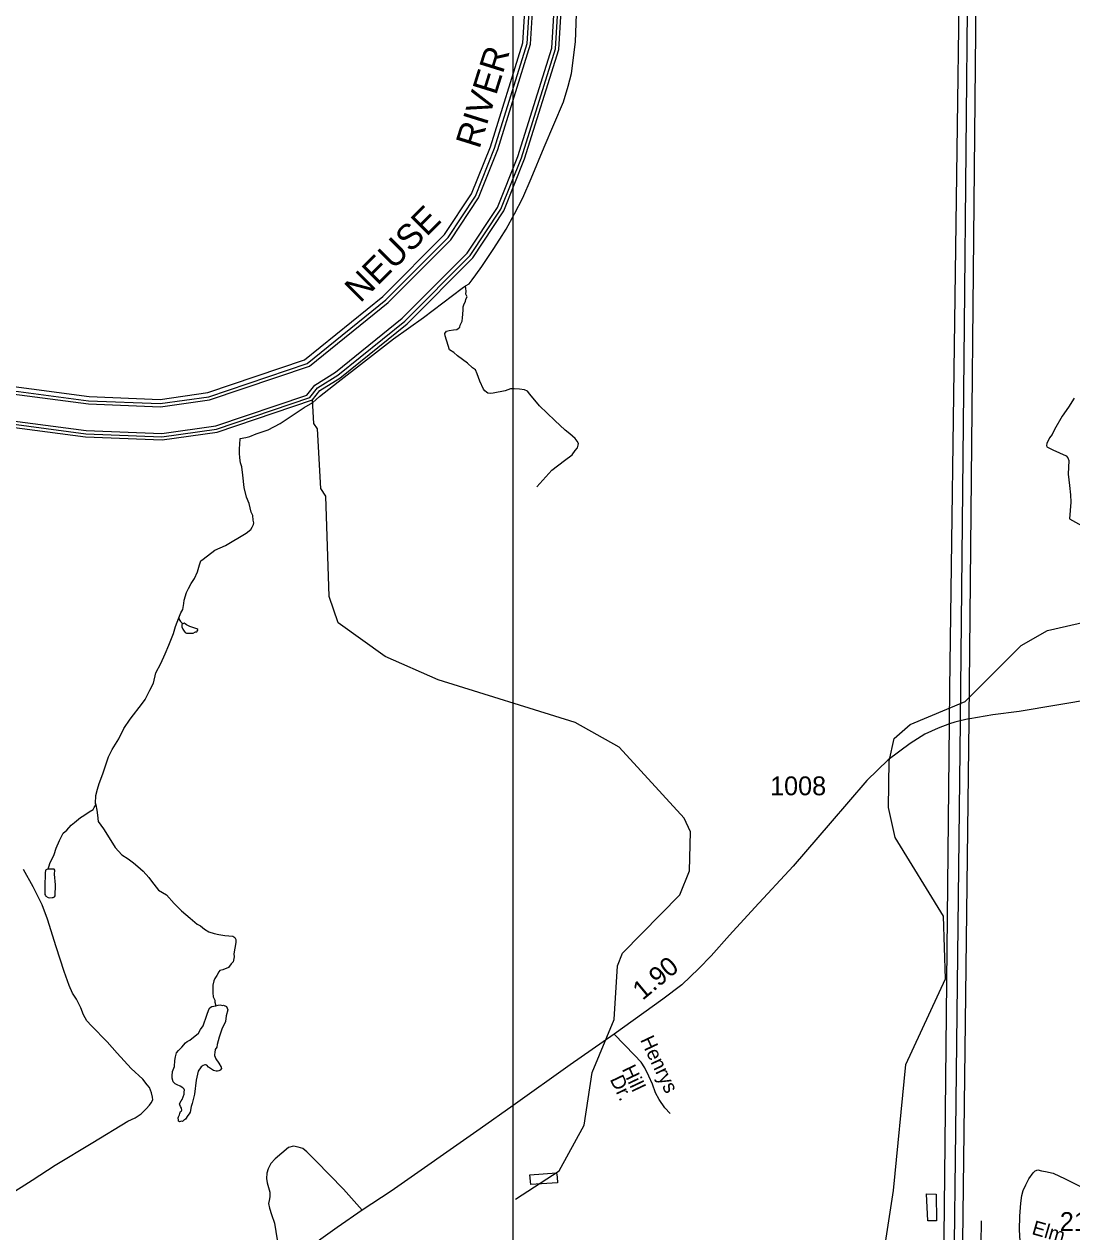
# Model space of a CAD drawing. Extents: x 2206922 to 2357709, y 510027 to 673830.
# Drawn here: x 2263859 to 2270812, y 583195 to 591205 of the extents above; entities that cross this region are included whole.
import ezdxf

# ---------------------------------------------------------------- set-up
doc = ezdxf.new("R2010")
doc.units = 0
for name, color, linetype in [('Exist Hydrographic Buffer Line', 7, 'Continuous'), ('Exist Hydrographic Creek Single Shore', 7, 'Continuous'), ('Exist Hydrographic Misc Water Feature', 7, 'Continuous'), ('Exist Hydrographic River Shore', 7, 'Continuous'), ('Exist Hydrographic River Shore Label', 7, 'Continuous'), ('Exist Road Non-System Type 51', 7, 'Continuous'), ('Exist Road Non-System Type 51 Label', 7, 'Continuous'), ('Exist Road Secondary Mileage Hundredths English Label', 7, 'Continuous'), ('Exist Road Secondary Type 51 Attributed', 7, 'Continuous'), ('Exist Road Secondary Type 51 Label', 7, 'Continuous'), ('Exist Road Secondary Type 51 Number Label', 7, 'Continuous'), ('Exist Utilities Electrical Transmission Line', 7, 'Continuous'), ('Map Preparation Inset Cut Line', 7, 'Continuous')]:
    doc.layers.add(name, color=color, linetype=linetype)

msp = doc.modelspace()

# ---------------------------------------------------------------- linework, layer by layer
at = {"layer": 'Exist Hydrographic Buffer Line'}
for points in [[(2265738.1, 588954.9), (2266258.8, 589376.1), (2266672.7, 589790.2), (2266854.1, 590065.1), (2266981.1, 590382.3), (2267198, 591076.7), (2267226.2, 591537.3), (2267426.9, 592727.2)], [(2265752.3, 588937.3), (2266273.9, 589359.2), (2266690.3, 589775.8), (2266874.3, 590054.5), (2267002.4, 590374.7), (2267220.4, 591072.6), (2267248.7, 591534.7), (2267449.3, 592723.5)], [(2265735, 588744.5), (2265789.1, 588811.1), (2265925.5, 588896.4), (2266368.2, 589254.5), (2266800, 589686.4), (2266999.6, 589989), (2267135.1, 590327.5), (2267359.8, 591047), (2267388.7, 591518.6), (2267586.4, 592690.4)], [(2265754.7, 588729.4), (2265805.7, 588792.3), (2265939.9, 588876.2), (2266384.8, 589236.1), (2266819.2, 589670.7), (2267021.7, 589977.4), (2267158.5, 590319.2), (2267384.3, 591042.4), (2267413.4, 591515.8), (2267610.4, 592683.8)], [(2260871, 587572.6), (2260946.2, 587608.4), (2260953.7, 587654.2), (2261804, 588398.4), (2262148.5, 588603.7), (2262761.1, 588772.7), (2262990.7, 588802.1), (2263521.7, 588808.8), (2264287.1, 588707.3), (2264762.3, 588688.4), (2265084.8, 588733.9), (2265738.1, 588954.9)], [(2260883.1, 587554.9), (2260965.4, 587594), (2260973.5, 587643.2), (2261816.6, 588381.1), (2262156.9, 588584.1), (2262765.3, 588751.8), (2262992.2, 588780.9), (2263520.5, 588787.5), (2264285.2, 588686.1), (2264763.4, 588667.2), (2265089.7, 588713.2), (2265752.3, 588937.3)], [(2261050.1, 587440), (2261131, 587509.5), (2261137.9, 587551.8), (2261921.1, 588237.3), (2262227.1, 588419.7), (2262800.2, 588577.7), (2263004.6, 588603.9), (2263509.9, 588610.3), (2264270.1, 588509.5), (2264772.3, 588489.6), (2265130.8, 588540.1), (2265735, 588744.5)], [(2261059.1, 587420.5), (2261150.1, 587498.8), (2261157.1, 587541.2), (2261933.2, 588220.5), (2262235.2, 588400.6), (2262804.3, 588557.5), (2263006, 588583.3), (2263508.6, 588589.7), (2264268.3, 588489), (2264773.4, 588468.9), (2265135.6, 588520), (2265754.7, 588729.4)]]:
    msp.add_lwpolyline(points, dxfattribs=at)
at = {"layer": 'Exist Hydrographic Creek Single Shore'}
msp.add_lwpolyline([(2267120.6, 583412.2), (2267410.6, 583599.8), (2267574.6, 583901.5), (2267629.6, 584251.4), (2267775.6, 584602.6), (2267797.5, 584959.7), (2267830.5, 585044.2), (2268209.5, 585430.1), (2268274.5, 585589.5), (2268280.6, 585848.5), (2268238.6, 585937.9), (2267808.6, 586409), (2267515.6, 586572.3), (2266605.5, 586856.4), (2266254.5, 587011.1), (2265943.4, 587233.9), (2265883.6, 587408.9), (2265860.6, 588075.1), (2265827.6, 588125), (2265806.5, 588522.3), (2265781.4, 588555.6), (2265771.6, 588713.2)], dxfattribs=at)
at = {"layer": 'Exist Hydrographic Misc Water Feature'}
for points in [[(2266787, 589469.4), (2266812.2, 589483.4), (2266832.3, 589509.6), (2266856.1, 589542.1), (2266895.7, 589598.2), (2266970.5, 589711), (2267015.8, 589779.2), (2267057.1, 589845.6), (2267114.1, 589948.1), (2267168.8, 590052.6), (2267223.8, 590181), (2267309.7, 590389.9), (2267439.1, 590690.7), (2267470.2, 590793.1), (2267491.4, 590877.1), (2267517, 591087.3), (2267528.3, 591397.5), (2267540.2, 591621.2), (2267594.5, 591981.6), (2267637, 592161.8), (2267688.4, 592430.2), (2267758.3, 592666.6), (2267758.1, 592678.8)], [(2265774.7, 588696.2), (2265820, 588736.8), (2265943.4, 588833.8), (2266112, 588963.3), (2266310.5, 589119.1), (2266508.8, 589258.7), (2266766.7, 589455), (2266787, 589469.4)], [(2267261.3, 588136.3), (2267361.8, 588247.3), (2267445.2, 588312.2), (2267495.1, 588348.5), (2267516.4, 588376.9), (2267530.5, 588395.1), (2267536.5, 588412.8), (2267538.5, 588425), (2267530.1, 588438.9), (2267515.8, 588456.9), (2267479.3, 588488.3), (2267449.5, 588511.8), (2267381, 588577.3), (2267280, 588674.5), (2267215.4, 588751.5), (2267199.2, 588771.4), (2267179.3, 588779.3), (2267146.9, 588785), (2267111.2, 588786.7), (2267087, 588786.7), (2267051.3, 588774.2), (2266971.6, 588757.5), (2266951.3, 588755.3), (2266935.5, 588757.2), (2266927.3, 588765), (2266917.2, 588773), (2266906.8, 588784.7), (2266882.8, 588836.5), (2266864.3, 588886.4), (2266854.1, 588912.2), (2266834, 588926.2), (2266801.4, 588955.9), (2266735.1, 589005.2), (2266710.7, 589026.7), (2266682.6, 589044.7), (2266672.4, 589074.7), (2266654.1, 589138.3), (2266651.7, 589154.1), (2266661.7, 589168.4), (2266679.8, 589174.6), (2266709.3, 589178.6), (2266729.6, 589180.8), (2266739.6, 589187), (2266749.5, 589195.3), (2266753, 589209.3), (2266765.1, 589235.1), (2266768.8, 589257.2), (2266772.2, 589309.4), (2266772, 589331.3), (2266778, 589351.2), (2266788, 589365.5), (2266789.5, 589381.5), (2266799.7, 589397.4), (2266791.1, 589415.2), (2266791.3, 589433.5), (2266787, 589469.4)], [(2265293, 588456.1), (2265330.9, 588464.2), (2265357.2, 588470.4), (2265398.8, 588488.8), (2265478.6, 588513.7), (2265557.9, 588556.5), (2265717, 588661.9), (2265774.7, 588696.2)], [(2270827.6, 588725.4), (2270790.4, 588665.3), (2270746.8, 588605), (2270697.6, 588516.3), (2270682, 588484.2), (2270664.3, 588462.1), (2270646.5, 588424.2), (2270642.6, 588410.2), (2270645.1, 588402.1), (2270686.7, 588382.4), (2270773.4, 588341.4), (2270785.5, 588329.5), (2270791.9, 588311.5), (2270788.4, 588219.5), (2270795.2, 588145.5), (2270803.6, 588083.8), (2270804.2, 588035.5), (2270797, 587923.8), (2270936, 587846.9)], [(2264886.4, 587266.8), (2264899.7, 587300.8), (2264911.8, 587322.9), (2264919.4, 587362.7), (2264921.2, 587384.8), (2264937, 587435.1), (2264950.6, 587463.1), (2264968.2, 587495.3), (2264989.9, 587529.3), (2265009.4, 587573.8), (2265022.9, 587619.7), (2265030.7, 587645.6), (2265046.7, 587655.8), (2265124, 587716.7), (2265195.8, 587747.2), (2265333.2, 587828.4), (2265362.7, 587852.7), (2265372.6, 587869), (2265380.1, 587887), (2265382.2, 587898.8), (2265378.1, 587914.9), (2265375.8, 587946.9), (2265365.4, 587968.7), (2265351.2, 588026.8), (2265334.8, 588068.6), (2265319.9, 588132.5), (2265309.2, 588214), (2265304.7, 588268.2), (2265294.4, 588296.1), (2265290.5, 588328), (2265288.1, 588359.9), (2265287.7, 588390), (2265289.7, 588417.7), (2265293, 588456.1)], [(2264332.1, 586036.3), (2264335.6, 586088.1), (2264345.2, 586132.2), (2264357.1, 586168.4), (2264380.1, 586232.7), (2264419.3, 586344.8), (2264442.4, 586394.8), (2264486.5, 586465.3), (2264521.6, 586533.7), (2264562.6, 586596.1), (2264643.8, 586702.7), (2264661.4, 586726.8), (2264693, 586786.9), (2264716.4, 586835.3), (2264732, 586903.6), (2264767, 586963.9), (2264794.7, 587029.9), (2264818.5, 587086), (2264849.5, 587164.4), (2264863, 587210.6), (2264886.4, 587266.8)], [(2264886.4, 587266.8), (2264888.6, 587256.7), (2264896.8, 587242.9), (2264912.8, 587227)], [(2269493.5, 582593.5), (2269627.6, 583469.7), (2269710.6, 584304.3), (2269972.5, 584873), (2269960.6, 585289.7), (2269638.7, 585811.2), (2269594.6, 586008.8), (2269600.5, 586317), (2269632.5, 586467.2), (2269739.6, 586560.1), (2270104.5, 586713.4), (2270476.5, 587083.1), (2270649.6, 587184.5), (2271007.6, 587265.8)], [(2264912.8, 587227), (2264905, 587223), (2264905.2, 587208.7), (2264911, 587192.8), (2264921, 587179.2), (2264927, 587171), (2264935.4, 587165.3), (2264941.3, 587165.2), (2264957.5, 587165.2), (2264981.3, 587165.6), (2264997.1, 587173.8), (2265005.1, 587175.8), (2265007.2, 587180), (2265011.1, 587185.9), (2265010.8, 587190), (2265004.7, 587193.8), (2264959, 587209.5), (2264937, 587221), (2264928.6, 587227.1), (2264920.8, 587233.2), (2264912.8, 587227)], [(2264018.4, 585601.5), (2264030.3, 585637.4), (2264057.8, 585697.8), (2264071.1, 585739.9), (2264093, 585791.8), (2264118.1, 585838.3), (2264141.8, 585858.6), (2264171.8, 585892.7), (2264193.5, 585910.9), (2264233.5, 585943.4), (2264254.8, 585957.6), (2264290.7, 585981.7), (2264316.5, 585996.2), (2264324.3, 586009.9), (2264334, 586026.5), (2264332.1, 586036.3)], [(2264332.1, 586036.3), (2264334, 586026.5), (2264340.5, 585992.1), (2264345, 585958.2), (2264351.2, 585916.3), (2264385.4, 585868.6), (2264422.3, 585809), (2264463.2, 585745.3), (2264507.2, 585696.1), (2264549.3, 585668.3), (2264583.7, 585642.8), (2264613.9, 585617.2), (2264648.5, 585587.2), (2264686.7, 585545.8), (2264704.9, 585519.9), (2264751.3, 585462.2), (2264804, 585430.8), (2264854.2, 585373.3), (2264902.6, 585323.8), (2264961, 585276.5), (2265007.6, 585235), (2265029.3, 585225.3), (2265056, 585203.4), (2265083.8, 585185.4), (2265119.9, 585173.9), (2265152.1, 585168.2), (2265191.9, 585160.6), (2265244.2, 585157.2), (2265256.1, 585147.3), (2265264.5, 585133.4), (2265264.5, 585113.1), (2265251, 585039.4), (2265253, 585019.2), (2265249.3, 584997.4), (2265245.2, 584985.1), (2265233.9, 584973), (2265214.1, 584948.8), (2265178.4, 584932.7), (2265158.5, 584928.4), (2265150.3, 584920.3), (2265138.8, 584894.5), (2265124.9, 584874.3), (2265116.9, 584860.1), (2265111.5, 584830.1), (2265111.7, 584780.1), (2265113.8, 584754.3), (2265124, 584732.1), (2265124.2, 584718.2), (2265130.6, 584694.2)], [(2264018.4, 585601.5), (2264014.5, 585601.3), (2264008.8, 585597.3), (2264000.4, 585593.2), (2263998.7, 585573.2), (2263997.3, 585485.4), (2263995.8, 585433.3), (2264000.1, 585425.4), (2264004, 585421.5), (2264018, 585413.3), (2264030.1, 585409.5), (2264044.2, 585411.9), (2264052.2, 585411.9), (2264060, 585418), (2264064.1, 585423.9), (2264067.6, 585495.9), (2264060.8, 585567.9), (2264062.5, 585593.6), (2264058.4, 585599.9), (2264052.4, 585601.6), (2264032.3, 585601.4), (2264022.5, 585601.3), (2264018.4, 585601.5)], [(2265130.6, 584694.2), (2265146, 584698.3), (2265160.5, 584700.6), (2265178.2, 584696.7), (2265182.3, 584698.9), (2265190.1, 584694.9), (2265194, 584694.7), (2265202.8, 584688.9), (2265210.6, 584667.1), (2265200.7, 584628.8), (2265195, 584589.1), (2265171.8, 584538.7), (2265152.5, 584486.5), (2265140.6, 584438.4), (2265136.8, 584420.7), (2265126.9, 584404.3), (2265125.3, 584384.3), (2265121.6, 584372.3), (2265121.6, 584364.6), (2265131.8, 584342.4), (2265149.9, 584312.9), (2265166.5, 584286.9), (2265168.5, 584278.8), (2265160.5, 584266.7), (2265150.5, 584262.5), (2265142.5, 584260.5), (2265134.3, 584260.5), (2265116.2, 584264.4), (2265082, 584288.2), (2265072.2, 584299.9), (2265062.1, 584303.8), (2265058, 584302), (2265046.3, 584297.7), (2265034.2, 584289.8), (2265014.7, 584261.5), (2265000.8, 584201.5), (2264989.9, 584107.1), (2264974.6, 584045.3), (2264966.8, 584027), (2264960.8, 583989), (2264953.4, 583977.1), (2264945.2, 583967), (2264929.4, 583943), (2264923.5, 583938.7), (2264917.8, 583934.7), (2264909.6, 583926.6), (2264902, 583928.5), (2264895.6, 583926.6), (2264889.7, 583924.3), (2264883.5, 583928.5), (2264883.7, 583936.6), (2264881.3, 583950.3), (2264883.5, 583958.4), (2264889.3, 583970.5), (2264891.3, 583980.4), (2264897.3, 583992.5), (2264903, 583996.5), (2264904.8, 584002.7), (2264903, 584014.7), (2264897, 584026.6), (2264892.7, 584036.6), (2264890.7, 584044.6), (2264900.7, 584064.6), (2264908.3, 584072.3), (2264920, 584108.7), (2264921.9, 584122.6), (2264923.9, 584134.5), (2264921.9, 584140.4), (2264911.6, 584150.5), (2264893.6, 584162.1), (2264875.3, 584170.2), (2264861.4, 584175.9), (2264853.4, 584186.1), (2264847.2, 584189.8), (2264841.1, 584213.8), (2264841.1, 584229.7), (2264842.7, 584257.8), (2264856, 584291.9), (2264858.1, 584331.7), (2264863.8, 584356), (2264869.4, 584381.9), (2264883.1, 584398.1), (2264900.9, 584416.1), (2264905, 584420.3), (2264930.7, 584448.5), (2264940.5, 584456.8), (2264958.8, 584466.6), (2265016.2, 584513.5), (2265030.1, 584537.4), (2265047.6, 584561.5), (2265070.7, 584631.8), (2265084.9, 584669.8), (2265090.4, 584677.9), (2265094.3, 584683.8), (2265104.8, 584689.9), (2265130.6, 584694.2)], [(2267396, 583558.3), (2267398.1, 583520.3), (2267220.7, 583508.5), (2267213.9, 583572.3), (2267391.7, 583586.1), (2267396, 583558.3)], [(2269855.2, 583267.5), (2269847.8, 583447.1), (2269911.6, 583445.6), (2269913, 583267.7), (2269855.2, 583267.5)]]:
    msp.add_lwpolyline(points, dxfattribs=at)
at = {"layer": 'Exist Hydrographic River Shore'}
for points in [[(2265719.2, 588978.2), (2266238.7, 589398.4), (2266649.4, 589809.3), (2266827.4, 590079.1), (2266952.8, 590392.4), (2267168.2, 591082.2), (2267196.3, 591540.7), (2267397.4, 592732.2)], [(2265771.6, 588713.2), (2265821.4, 588774.5), (2265953.5, 588857.1), (2266400.5, 589218.6), (2266837.5, 589655.8), (2267042.5, 589966.5), (2267180.5, 590311.4), (2267407.5, 591038.2), (2267436.6, 591513.1), (2267633.5, 592679.9)], [(2260847.5, 587592.6), (2260920.9, 587627.5), (2260927.6, 587668.7), (2261787.4, 588421.2), (2262137.4, 588629.9), (2262755.5, 588800.3), (2262988.7, 588830.2), (2263523.4, 588836.9), (2264289.5, 588735.4), (2264760.9, 588716.7), (2265078.3, 588761.4), (2265719.2, 588978.2)], [(2261061.3, 587395), (2261169.4, 587488), (2261176.4, 587530.5), (2261945.5, 588203.6), (2262243.5, 588381.3), (2262808.4, 588537.1), (2263007.5, 588562.5), (2263507.4, 588568.8), (2264266.5, 588468.2), (2264774.4, 588448.1), (2265140.4, 588499.7), (2265771.6, 588713.2)]]:
    msp.add_lwpolyline(points, dxfattribs=at)
at = {"layer": 'Exist Road Non-System Type 51'}
for points in [[(2263748.3, 583433.8), (2263913.1, 583537.8), (2264065.5, 583636.2), (2264314.9, 583787.3), (2264547.6, 583928.6), (2264596.1, 583952.2), (2264636.3, 583977.1), (2264669.5, 584010.4), (2264691.7, 584035.4), (2264702.8, 584050.6), (2264712.5, 584070), (2264709.7, 584088), (2264704.2, 584117.1), (2264691.7, 584151.8), (2264676.5, 584169.8), (2264646, 584207.2), (2264568.4, 584277.9), (2264477, 584380.5), (2264409.1, 584455.4), (2264306.6, 584560.7), (2264274.7, 584595.4), (2264252.5, 584634.2), (2264234.5, 584681.3), (2264206.8, 584738.1), (2264179.1, 584778.3), (2264157, 584829.6), (2264125.1, 584922.5), (2264071.1, 585086), (2264014.3, 585269), (2263978.2, 585364.6), (2263918.7, 585483.9), (2263854.9, 585597.5)], [(2268145.7, 583980.8), (2268111.5, 584016.5), (2268073, 584072), (2268048.5, 584117.7), (2268028.1, 584175.5), (2268005.6, 584227.3), (2267979.1, 584283.1), (2267954.7, 584320.7), (2267908.4, 584366.3), (2267775.1, 584507.1)], [(2266103, 583338), (2265978.7, 583478.5), (2265795.8, 583665.6), (2265735.5, 583726.3), (2265707.4, 583748), (2265677.2, 583757.6), (2265647.3, 583763.4), (2265613.4, 583755.1), (2265524.1, 583678.4), (2265496.5, 583648.1), (2265478.8, 583613.9), (2265469, 583583.9), (2265467.3, 583549.8), (2265471.7, 583519.9), (2265479.9, 583489.9), (2265490.2, 583458.1), (2265490.4, 583428.1), (2265484.7, 583402.1), (2265480.9, 583382.1), (2265487.3, 583352.2), (2265501.6, 583310.3), (2265520.1, 583252.6), (2265539.2, 583142.7), (2265580.7, 582977.3)], [(2270469.5, 583133.2), (2270464.7, 583207.3), (2270466.4, 583299.7), (2270473, 583385.6), (2270479.6, 583435.1), (2270489.5, 583469.8), (2270506, 583506.1), (2270527.4, 583547.3), (2270555.5, 583585.3), (2270568.7, 583600.2), (2270585.1, 583606.8), (2270611.5, 583600.2), (2270637.9, 583595.2), (2270687.4, 583583.7), (2270768.3, 583547.3), (2270868.9, 583496.2)], [(2270083.4, 582946.9), (2270146.3, 582958.1), (2270184.3, 582968.6), (2270194.1, 582972.6), (2270198.1, 582978.7), (2270202, 582994.6), (2270210.8, 583112.6), (2270213.3, 583268.7)]]:
    msp.add_lwpolyline(points, dxfattribs=at)
at = {"layer": 'Exist Road Secondary Type 51 Attributed'}
msp.add_lwpolyline([(2270961.7, 586730.3), (2270461.5, 586647.1), (2270287.7, 586623.5), (2270134, 586598), (2270128.2, 586596.8), (2270070.3, 586584.2), (2270034.9, 586576.5), (2269999.9, 586563.6), (2269924.9, 586536), (2269837.3, 586495.2), (2269737.9, 586434.5), (2269592.3, 586324.9), (2269451, 586187.7), (2269207.2, 585905.8), (2268962, 585621.5), (2268708.7, 585347.3), (2268540.5, 585163.8), (2268417.9, 585024.7), (2268336.7, 584942), (2268222.9, 584834.1), (2268096.7, 584737.9), (2267775.1, 584507.1), (2267483.1, 584302.3), (2267104.4, 584034), (2266885.6, 583878.9), (2266295.7, 583465.6), (2266103, 583338), (2265936.1, 583224.4), (2265709.7, 583062.4)], dxfattribs=at)
at = {"layer": 'Exist Utilities Electrical Transmission Line'}
msp.add_line((2270188.8, 592699.3), (2270128.2, 586596.8), dxfattribs=at)
for points in [[(2269999.9, 586563.6), (2270002.4, 586798.8), (2270078.4, 592320.5), (2270082.8, 592698.3)], [(2270130.8, 592698.7), (2270097.6, 589206.3), (2270070.3, 586584.2)], [(2269939.7, 580926), (2269968.7, 583568.1), (2269999.9, 586563.6)], [(2270070.3, 586584.2), (2270070.3, 586577.5), (2270039.9, 583866.7), (2270028.3, 582928.9)], [(2270128.2, 586596.8), (2270128.2, 586587.9), (2270083.4, 582946.9)]]:
    msp.add_lwpolyline(points, dxfattribs=at)
at = {"layer": 'Map Preparation Inset Cut Line'}
for p, q in [((2267104.4, 584034), (2267104.4, 593654.9)), ((2267104.4, 578317.9), (2267104.4, 584034))]:
    msp.add_line(p, q, dxfattribs=at)

# ---------------------------------------------------------------- texts
at = {"layer": 'Exist Hydrographic River Shore Label'}
for s, rotation, p in [('RIVER', 72.65563, (2266879.8, 590373)), ('NEUSE', 45.01344, (2266090.1, 589351.9))]:
    msp.add_text(s, height=167.32, rotation=rotation, dxfattribs=at).set_placement(p)
at = {"layer": 'Exist Road Non-System Type 51 Label'}
for s, p in [('Henrys', (2267945.4, 584468.7)), ('Hill', (2267823.5, 584274.6)), ('Dr.', (2267744.3, 584207))]:
    msp.add_text(s, height=95, rotation=295.40277, dxfattribs=at).set_placement(p)
at = {"layer": 'Exist Road Secondary Mileage Hundredths English Label'}
msp.add_text('1.90', height=125, rotation=39.90496, dxfattribs=at).set_placement((2267963.2, 584726.6))
at = {"layer": 'Exist Road Secondary Type 51 Label'}
msp.add_text('Elm', height=95, rotation=343.86056, dxfattribs=at).set_placement((2270540.7, 583181.2))
at = {"layer": 'Exist Road Secondary Type 51 Number Label'}
for s, p in [('1008', (2268809.3, 586090.7)), ('2113', (2270731.9, 583200.7))]:
    msp.add_text(s, height=125, dxfattribs=at).set_placement(p)

doc.saveas('drawing.dxf')
